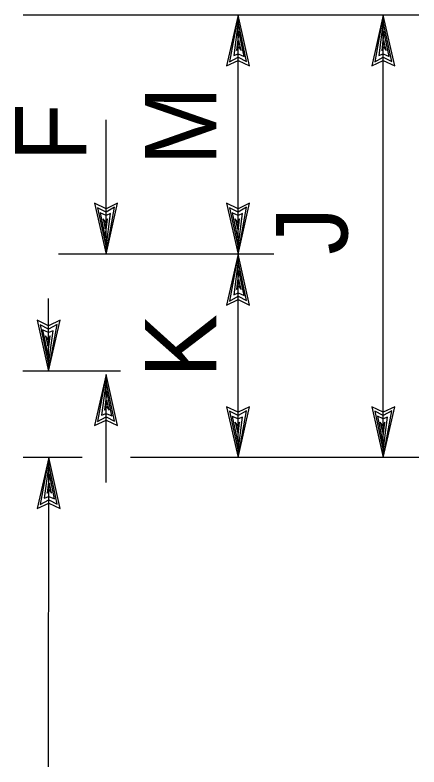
# Model space of a CAD drawing. Extents: x -0.08 to 2.83, y -0.03 to 1.92.
# Drawn here: x 1.0569 to 1.1305, y 1.4449 to 1.582 of the extents above; entities that cross this region are included whole.
import ezdxf

# ---------------------------------------------------------------- set-up
doc = ezdxf.new("R2010")
doc.units = 0
doc.layers.add('55', color=7, linetype='Continuous')
doc.layers.add('57', color=7, linetype='Continuous')

msp = doc.modelspace()

# ---------------------------------------------------------------- linework, layer by layer
at = {"layer": '55'}
for p, q in [((1.13052, 1.58196), (1.05836, 1.58196)), ((1.09756, 1.58196), (1.09547, 1.57268)), ((1.09756, 1.58196), (1.09601, 1.57341)), ((1.09964, 1.57268), (1.09756, 1.58196)), ((1.09756, 1.50131), (1.09756, 1.58196)), ((1.12401, 1.58196), (1.12192, 1.57268)), ((1.12401, 1.58196), (1.12246, 1.57341)), ((1.12401, 1.50131), (1.12401, 1.58196)), ((1.12609, 1.57268), (1.12401, 1.58196)), ((1.09756, 1.58075), (1.09675, 1.57456)), ((1.09911, 1.57348), (1.09756, 1.58075)), ((1.12401, 1.58075), (1.1232, 1.57456)), ((1.12555, 1.57348), (1.12401, 1.58075)), ((1.0977, 1.579), (1.09729, 1.5755)), ((1.09864, 1.57443), (1.0977, 1.579)), ((1.12414, 1.579), (1.12374, 1.5755)), ((1.12509, 1.57443), (1.12414, 1.579)), ((1.09809, 1.5755), (1.0977, 1.57731)), ((1.0977, 1.57731), (1.0977, 1.57644)), ((1.12454, 1.5755), (1.12414, 1.57731)), ((1.12414, 1.57731), (1.12414, 1.57644)), ((1.09729, 1.5755), (1.09763, 1.57617)), ((1.09763, 1.57617), (1.09809, 1.5755)), ((1.12374, 1.5755), (1.12407, 1.57617)), ((1.12407, 1.57617), (1.12454, 1.5755)), ((1.09601, 1.57341), (1.09756, 1.57429)), ((1.09675, 1.57456), (1.09756, 1.5749)), ((1.09756, 1.5749), (1.09864, 1.57443)), ((1.09756, 1.57429), (1.09911, 1.57348)), ((1.12246, 1.57341), (1.12401, 1.57429)), ((1.1232, 1.57456), (1.12401, 1.5749)), ((1.12401, 1.5749), (1.12509, 1.57443)), ((1.12401, 1.57429), (1.12555, 1.57348)), ((1.09547, 1.57268), (1.09756, 1.57369)), ((1.09756, 1.57369), (1.09964, 1.57268)), ((1.12192, 1.57268), (1.12401, 1.57369)), ((1.12401, 1.57369), (1.12609, 1.57268)), ((1.07349, 1.53839), (1.07349, 1.56286)), ((1.07349, 1.54665), (1.07141, 1.54765)), ((1.07141, 1.54765), (1.07349, 1.53839)), ((1.07349, 1.53839), (1.07557, 1.54765)), ((1.07557, 1.54765), (1.07349, 1.54665)), ((1.07349, 1.53839), (1.07504, 1.54692)), ((1.07504, 1.54692), (1.07349, 1.54604)), ((1.09755, 1.54665), (1.09547, 1.54765)), ((1.09547, 1.54765), (1.09755, 1.53839)), ((1.09755, 1.53839), (1.09963, 1.54765)), ((1.09963, 1.54765), (1.09755, 1.54665)), ((1.09755, 1.53839), (1.0991, 1.54692)), ((1.0991, 1.54692), (1.09755, 1.54604)), ((1.07349, 1.54604), (1.07194, 1.54685)), ((1.07194, 1.54685), (1.07349, 1.53959)), ((1.07349, 1.54544), (1.07241, 1.54591)), ((1.07241, 1.54591), (1.07335, 1.54134)), ((1.07349, 1.53959), (1.07429, 1.54577)), ((1.07429, 1.54577), (1.07349, 1.54544)), ((1.09755, 1.54604), (1.09601, 1.54685)), ((1.09601, 1.54685), (1.09755, 1.53959)), ((1.09755, 1.54544), (1.09648, 1.54591)), ((1.09648, 1.54591), (1.09742, 1.54134)), ((1.09755, 1.53959), (1.09836, 1.54577)), ((1.09836, 1.54577), (1.09755, 1.54544)), ((1.07342, 1.54416), (1.07295, 1.54484)), ((1.07295, 1.54484), (1.07335, 1.54302)), ((1.07335, 1.54134), (1.07375, 1.54484)), ((1.07375, 1.54484), (1.07342, 1.54416)), ((1.09748, 1.54416), (1.09702, 1.54484)), ((1.09702, 1.54484), (1.09742, 1.54302)), ((1.09742, 1.54134), (1.09782, 1.54484)), ((1.09782, 1.54484), (1.09748, 1.54416)), ((1.07335, 1.54302), (1.07335, 1.5439)), ((1.09742, 1.54302), (1.09742, 1.5439)), ((1.10407, 1.53839), (1.06483, 1.53839)), ((1.09756, 1.53839), (1.09547, 1.52911)), ((1.09756, 1.53839), (1.09601, 1.52984)), ((1.09964, 1.52911), (1.09756, 1.53839)), ((1.09756, 1.53718), (1.09675, 1.53099)), ((1.09911, 1.52992), (1.09756, 1.53718)), ((1.0977, 1.53543), (1.09729, 1.53193)), ((1.09864, 1.53086), (1.0977, 1.53543)), ((1.09809, 1.53193), (1.0977, 1.53374)), ((1.0977, 1.53374), (1.0977, 1.53287)), ((1.09729, 1.53193), (1.09763, 1.5326)), ((1.09763, 1.5326), (1.09809, 1.53193)), ((1.09601, 1.52984), (1.09756, 1.53072)), ((1.09675, 1.53099), (1.09756, 1.53133)), ((1.09756, 1.53133), (1.09864, 1.53086)), ((1.09756, 1.53072), (1.09911, 1.52992)), ((1.06302, 1.51704), (1.06302, 1.53029)), ((1.09547, 1.52911), (1.09756, 1.53012)), ((1.09756, 1.53012), (1.09964, 1.52911)), ((1.06302, 1.52531), (1.06093, 1.52633)), ((1.06093, 1.52633), (1.06302, 1.51704)), ((1.06302, 1.51704), (1.0651, 1.52633)), ((1.0651, 1.52633), (1.06302, 1.52531)), ((1.06302, 1.5247), (1.06147, 1.52551)), ((1.06147, 1.52551), (1.06302, 1.51826)), ((1.06302, 1.51704), (1.06456, 1.52558)), ((1.06456, 1.52558), (1.06302, 1.5247)), ((1.06302, 1.5241), (1.06193, 1.52457)), ((1.06193, 1.52457), (1.06288, 1.52)), ((1.06302, 1.51826), (1.06383, 1.52444)), ((1.06383, 1.52444), (1.06302, 1.5241)), ((1.06295, 1.52283), (1.06248, 1.5235)), ((1.06248, 1.5235), (1.06288, 1.52168)), ((1.06288, 1.52), (1.06328, 1.5235)), ((1.06288, 1.52168), (1.06288, 1.52256)), ((1.06328, 1.5235), (1.06295, 1.52283)), ((1.07611, 1.51704), (1.05835, 1.51705)), ((1.07349, 1.51643), (1.07141, 1.50716)), ((1.07349, 1.51643), (1.07195, 1.50789)), ((1.07558, 1.50716), (1.07349, 1.51643)), ((1.07349, 1.49675), (1.07349, 1.51643)), ((1.07349, 1.51522), (1.07268, 1.50904)), ((1.07504, 1.50796), (1.07349, 1.51522)), ((1.07363, 1.51347), (1.07322, 1.50998)), ((1.07457, 1.5089), (1.07363, 1.51347)), ((1.07403, 1.50998), (1.07363, 1.51179)), ((1.07363, 1.51179), (1.07363, 1.51092)), ((1.07322, 1.50998), (1.07356, 1.51065)), ((1.07356, 1.51065), (1.07403, 1.50998)), ((1.09756, 1.50957), (1.09547, 1.51057)), ((1.09547, 1.51057), (1.09756, 1.50131)), ((1.09756, 1.50131), (1.09964, 1.51057)), ((1.09964, 1.51057), (1.09756, 1.50957)), ((1.12401, 1.50957), (1.12192, 1.51059)), ((1.12192, 1.51059), (1.12401, 1.50131)), ((1.12401, 1.50131), (1.12609, 1.51059)), ((1.12609, 1.51059), (1.12401, 1.50957)), ((1.07195, 1.50789), (1.07349, 1.50877)), ((1.07268, 1.50904), (1.07349, 1.50937)), ((1.07349, 1.50937), (1.07457, 1.5089)), ((1.07349, 1.50877), (1.07504, 1.50796)), ((1.09756, 1.50896), (1.09601, 1.50977)), ((1.09601, 1.50977), (1.09756, 1.50251)), ((1.09756, 1.50836), (1.09648, 1.50883)), ((1.09648, 1.50883), (1.09743, 1.50426)), ((1.09756, 1.50131), (1.09911, 1.50984)), ((1.09911, 1.50984), (1.09756, 1.50896)), ((1.09756, 1.50251), (1.09837, 1.50869)), ((1.09837, 1.50869), (1.09756, 1.50836)), ((1.12401, 1.50897), (1.12246, 1.50978)), ((1.12246, 1.50978), (1.12401, 1.50252)), ((1.12401, 1.50836), (1.12293, 1.50884)), ((1.12293, 1.50884), (1.12387, 1.50427)), ((1.12401, 1.50131), (1.12555, 1.50984)), ((1.12555, 1.50984), (1.12401, 1.50897)), ((1.12401, 1.50252), (1.12481, 1.5087)), ((1.12481, 1.5087), (1.12401, 1.50836)), ((1.07141, 1.50716), (1.07349, 1.50816)), ((1.07349, 1.50816), (1.07558, 1.50716)), ((1.09749, 1.50708), (1.09702, 1.50776)), ((1.09702, 1.50776), (1.09743, 1.50594)), ((1.09743, 1.50426), (1.09783, 1.50776)), ((1.09783, 1.50776), (1.09749, 1.50708)), ((1.12394, 1.50709), (1.12347, 1.50776)), ((1.12347, 1.50776), (1.12387, 1.50594)), ((1.12387, 1.50427), (1.12428, 1.50776)), ((1.12428, 1.50776), (1.12394, 1.50709)), ((1.09743, 1.50594), (1.09743, 1.50681)), ((1.12387, 1.50594), (1.12387, 1.50682)), ((1.06911, 1.50131), (1.05836, 1.50131)), ((1.06303, 1.50131), (1.06093, 1.49203)), ((1.06303, 1.50131), (1.06148, 1.49278)), ((1.06301, 1.44494), (1.06303, 1.50131)), ((1.0651, 1.49203), (1.06303, 1.50131)), ((1.13052, 1.50131), (1.07792, 1.50131)), ((1.06303, 1.5001), (1.06222, 1.49391)), ((1.06457, 1.49284), (1.06303, 1.5001)), ((1.06316, 1.49835), (1.06275, 1.49486)), ((1.0641, 1.49378), (1.06316, 1.49835)), ((1.06356, 1.49486), (1.06316, 1.49667)), ((1.06316, 1.49667), (1.06316, 1.49579)), ((1.06275, 1.49486), (1.06309, 1.49553)), ((1.06309, 1.49553), (1.06356, 1.49486)), ((1.06148, 1.49278), (1.06303, 1.49364)), ((1.06222, 1.49391), (1.06303, 1.49425)), ((1.06303, 1.49425), (1.0641, 1.49378)), ((1.06303, 1.49364), (1.06457, 1.49284)), ((1.06093, 1.49203), (1.06303, 1.49304)), ((1.06303, 1.49304), (1.0651, 1.49203))]:
    msp.add_line(p, q, dxfattribs=at)

# ---------------------------------------------------------------- texts
at = {"layer": '57'}
for s, rotation, p in [('M', 89.9967, (1.09359, 1.55452)), ('F', 89.9967, (1.06992, 1.55525)), ('J', 89.9966, (1.1175, 1.53827)), ('K', 89.9967, (1.09359, 1.51584))]:
    msp.add_text(s, height=0.01302, rotation=rotation, dxfattribs=at).set_placement(p)

doc.saveas('drawing.dxf')
